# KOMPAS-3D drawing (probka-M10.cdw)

Views: Вид 1, Вид 2, Выносной элемент А, Выносной элемент
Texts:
  Пробка М10х1
  *Размер для справок.
Dimensions and other numbers on the sheet: 14; 16,17; 18; 10; 2; 8,5; 0,3; 0,5; 13; 1; 6,3; 12,5; 2:1; 0,01; 0; 3; 4; 5; 6; 7; 8; 9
